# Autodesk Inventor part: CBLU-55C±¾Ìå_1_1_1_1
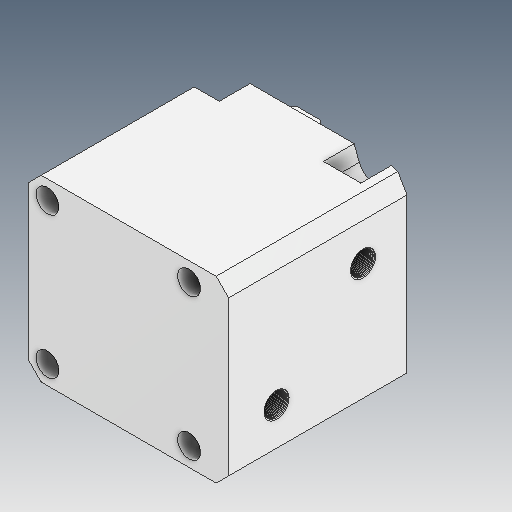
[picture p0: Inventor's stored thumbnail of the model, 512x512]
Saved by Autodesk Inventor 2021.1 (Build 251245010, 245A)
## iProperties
Created: 2021-05
Part Number: CBLU-55C±¾Ìå_1_1_1_1
Material: Ogólny
Document SubType Name: Modeling
Designer: user
Density: 1 g/cm^3
Appearance: Domyślna
Author: user
Revision Number: ÈÎºÎ
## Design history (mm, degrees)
feature "ÊäÈë1"
feature "ÊäÈë2"
feature "ÊäÈë3"
feature "ÊäÈë4"
node "Bryła1"
node "Bryła2"
node "Bryła3"
node "Bryła4"
